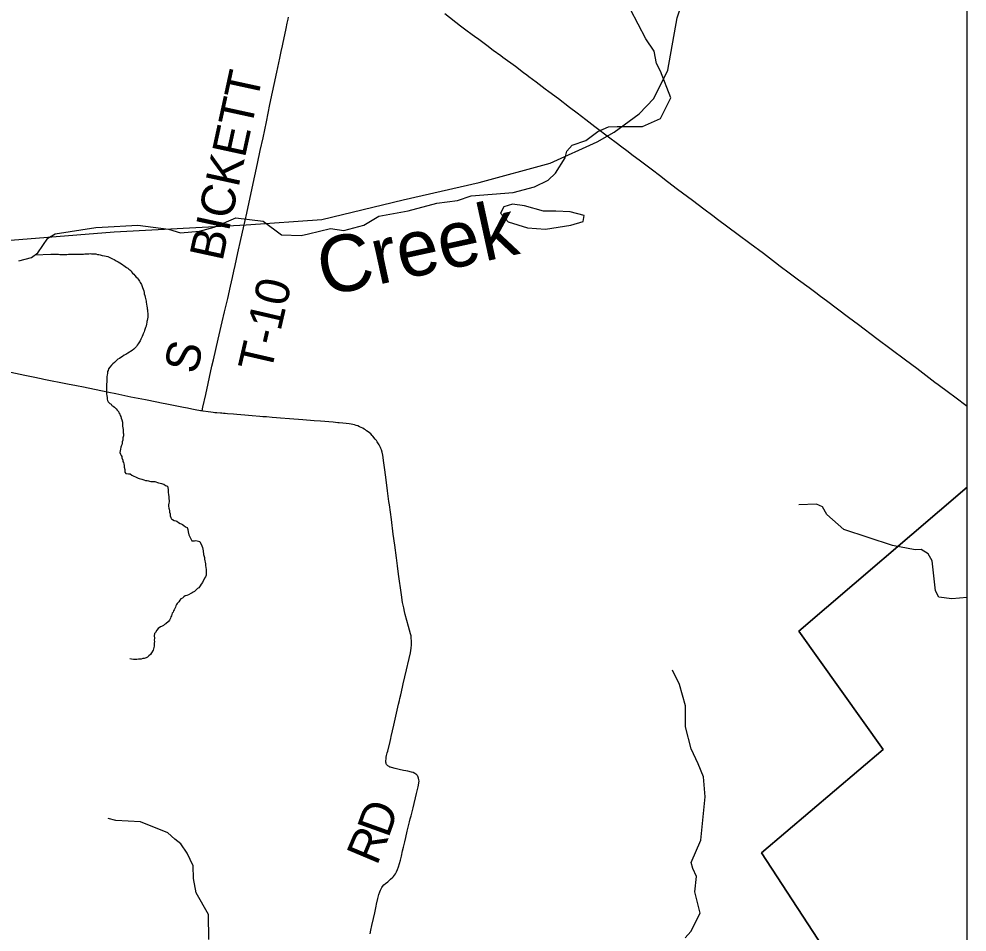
# Model space of a CAD drawing. Extents: x -1.4 to 35.4, y 0 to 22.
# Drawn here: x 14.841 to 16.43, y 16.794 to 18.324 of the extents above; entities that cross this region are included whole.
import ezdxf

# ---------------------------------------------------------------- set-up
doc = ezdxf.new("R2010")
doc.units = 0
for name, color, linetype in [('GM_X_County_Road', 7, 'Continuous'), ('GM_X_Minor_Lake', 7, 'Continuous'), ('GM_X_Minor_River', 7, 'Continuous'), ('GM_X_Minor_River_Text', 7, 'Continuous'), ('GM_X_Rail_Line', 7, 'Continuous'), ('GM_X_Township_Road', 7, 'Continuous'), ('GM_X_Township_Road_Text', 7, 'Continuous'), ('SC_Scratch1', 7, 'Continuous'), ('SH_Border', 7, 'Continuous')]:
    doc.layers.add(name, color=color, linetype=linetype)

msp = doc.modelspace()

# ---------------------------------------------------------------- linework, layer by layer
at = {"layer": 'GM_X_County_Road'}
msp.add_lwpolyline([(16.4299, 17.6747), (16.4096, 17.6899), (16.3991, 17.6977), (16.3817, 17.7106), (16.3762, 17.7147), (16.3455, 17.7379), (16.3266, 17.7521), (16.2789, 17.7879), (16.2483, 17.8113), (16.2314, 17.8239), (16.1945, 17.8514), (16.1845, 17.8588), (16.1766, 17.8648), (16.1652, 17.8734), (16.1476, 17.8862), (16.1317, 17.898), (16.1168, 17.9093), (16.1089, 17.9153), (16.0886, 17.9308), (16.0657, 17.9478), (16.0463, 17.9623), (16.012, 17.988), (16.004, 17.9939), (15.9891, 18.0052), (15.9698, 18.0197), (15.945, 18.0384), (15.9282, 18.0513), (15.9144, 18.0619), (15.9028, 18.0707), (15.8807, 18.0874), (15.8706, 18.0947), (15.8598, 18.1028), (15.8513, 18.1091), (15.8419, 18.1163), (15.8315, 18.1242), (15.8064, 18.1435), (15.7911, 18.1551), (15.7768, 18.1661), (15.7639, 18.1758), (15.7451, 18.19), (15.7291, 18.2018), (15.7232, 18.2063), (15.7078, 18.2179), (15.6959, 18.2269), (15.692, 18.23), (15.6865, 18.234), (15.6731, 18.2442), (15.6522, 18.2597), (15.6487, 18.2623), (15.6361, 18.2714), (15.625, 18.2795), (15.6117, 18.2894), (15.6047, 18.2946), (15.6007, 18.2976), (15.5903, 18.3054), (15.5814, 18.3122), (15.5547, 18.3324)], dxfattribs=at)
at = {"layer": 'GM_X_Minor_Lake'}
for points in [[(15.6885, 18.011), (15.6684, 18.0136), (15.6535, 18.0089), (15.648, 17.9988), (15.661, 17.9838), (15.6935, 17.9741), (15.7235, 17.972), (15.7661, 17.9782), (15.7867, 17.9843), (15.7884, 17.9949), (15.765, 18.001), (15.7411, 18.0017), (15.7202, 18.0021)], [(15.7202, 18.0021), (15.6885, 18.011)]]:
    msp.add_lwpolyline(points, dxfattribs=at)
at = {"layer": 'GM_X_Minor_River'}
for points in [[(14.9805, 17.9749), (15.0405, 17.9785), (15.0917, 17.9715), (15.1117, 17.9658), (15.1436, 17.9683), (15.1681, 17.9751), (15.2044, 17.9905), (15.2506, 17.9851), (15.281, 17.9625), (15.314, 17.9612), (15.3266, 17.964), (15.3632, 17.9729), (15.3859, 17.9695), (15.4191, 17.9784), (15.4444, 17.9935), (15.4932, 18.0026), (15.5412, 18.0151), (15.5759, 18.0198), (15.5988, 18.0277), (15.6691, 18.033), (15.705, 18.0426), (15.7283, 18.054), (15.7403, 18.0656), (15.7567, 18.0915), (15.7595, 18.1025), (15.768, 18.1126), (15.791, 18.1205), (15.811, 18.1354), (15.8293, 18.1434), (15.8438, 18.1436), (15.8859, 18.144), (15.9161, 18.1575), (15.9334, 18.1918), (15.916, 18.2365), (15.9097, 18.2495), (15.9055, 18.2701), (15.8918, 18.2909), (15.8532, 18.3648)], [(14.8409, 17.9188), (14.8623, 17.9245), (14.8727, 17.9323), (14.8898, 17.9567), (14.9021, 17.9641), (14.9702, 17.9743), (14.9805, 17.9749)], [(14.8683, 17.9285), (14.8945, 17.9296), (14.8987, 17.9299), (14.9021, 17.9299), (14.9055, 17.9299), (14.9074, 17.9299), (14.91, 17.9294), (14.9131, 17.929), (14.9157, 17.929), (14.9184, 17.929), (14.9214, 17.9294), (14.9241, 17.9297), (14.9271, 17.9297), (14.929, 17.93), (14.9313, 17.93), (14.9339, 17.93), (14.9358, 17.93), (14.9377, 17.93), (14.94, 17.9299), (14.943, 17.9299), (14.9453, 17.9299), (14.9472, 17.9299), (14.9495, 17.9299), (14.9514, 17.9302), (14.9544, 17.9306), (14.9563, 17.9302), (14.9586, 17.9305), (14.9605, 17.9309), (14.9631, 17.9305), (14.9673, 17.9301), (14.9703, 17.9301), (14.973, 17.9293), (14.9752, 17.9293), (14.9771, 17.9289), (14.979, 17.9281), (14.9809, 17.9277), (14.9847, 17.9273), (14.99, 17.9257), (14.9926, 17.9246), (14.996, 17.923), (14.9979, 17.9222), (15.0006, 17.9207), (15.0024, 17.9195), (15.0043, 17.9188), (15.0073, 17.9168), (15.0104, 17.9153), (15.013, 17.9138), (15.0153, 17.9118), (15.0172, 17.9107), (15.019, 17.9091), (15.0217, 17.9072), (15.0236, 17.9061), (15.0254, 17.9049), (15.0285, 17.9022), (15.03, 17.9003), (15.0318, 17.898), (15.0337, 17.8961), (15.0356, 17.8938), (15.0375, 17.8915), (15.0393, 17.89), (15.0408, 17.8877), (15.0435, 17.8843), (15.0446, 17.8824), (15.0465, 17.8789), (15.048, 17.8759), (15.0483, 17.874), (15.0494, 17.8709), (15.0505, 17.8683), (15.0509, 17.8656), (15.0513, 17.8633), (15.052, 17.8607), (15.0527, 17.858), (15.0535, 17.8557), (15.0542, 17.8511), (15.0546, 17.8492), (15.0549, 17.8458), (15.0556, 17.8428), (15.056, 17.8401), (15.056, 17.8382), (15.0564, 17.8363), (15.0567, 17.8329), (15.0571, 17.831), (15.057, 17.8276), (15.057, 17.8242), (15.0566, 17.8215), (15.0562, 17.8189), (15.0558, 17.817), (15.0558, 17.8151), (15.055, 17.8128), (15.0542, 17.809), (15.0535, 17.8071), (15.0523, 17.8037), (15.0519, 17.8018), (15.0508, 17.7999), (15.0496, 17.7965), (15.0488, 17.7946), (15.0477, 17.792), (15.0465, 17.7897), (15.0453, 17.7871), (15.0442, 17.7848), (15.0423, 17.7814)], [(15.0423, 17.7814), (15.0411, 17.7795), (15.0396, 17.7773), (15.038, 17.775), (15.0357, 17.7724), (15.0335, 17.7705), (15.0312, 17.7682), (15.0239, 17.7637), (15.022, 17.763), (15.0201, 17.7615), (15.0178, 17.7604), (15.0148, 17.7585), (15.0117, 17.7566), (15.0095, 17.7551), (15.0072, 17.7536), (15.0049, 17.7518), (15.003, 17.7499), (15.0011, 17.748), (14.9988, 17.7461), (14.9961, 17.7439), (14.9934, 17.7405), (14.9915, 17.7375), (14.9907, 17.7348), (14.9899, 17.7329), (14.9895, 17.7303), (14.9891, 17.7268), (14.9887, 17.7246), (14.9887, 17.7219), (14.9887, 17.7196), (14.9887, 17.7177), (14.9883, 17.7151), (14.9879, 17.7124), (14.9879, 17.7102), (14.9882, 17.7075), (14.9878, 17.7056), (14.9882, 17.6995), (14.9881, 17.6976), (14.9881, 17.6957), (14.9885, 17.6923), (14.9888, 17.6897), (14.9892, 17.687), (14.9899, 17.6847), (14.9907, 17.6824), (14.9933, 17.6797), (14.9956, 17.6782), (14.9971, 17.6763), (14.9993, 17.6748), (15.0016, 17.6732), (15.0042, 17.6705), (15.0057, 17.6686), (15.008, 17.666), (15.0087, 17.6637), (15.0102, 17.6618), (15.011, 17.6595), (15.0121, 17.6576), (15.0128, 17.6549), (15.0136, 17.6522), (15.0147, 17.6484), (15.015, 17.6446), (15.015, 17.6416), (15.0153, 17.6386), (15.0157, 17.6359), (15.0157, 17.634), (15.016, 17.6306), (15.0164, 17.6287), (15.0164, 17.6253), (15.0156, 17.6222), (15.0156, 17.6203), (15.0155, 17.6181), (15.0144, 17.6154), (15.014, 17.6131), (15.0136, 17.6101), (15.0128, 17.6082), (15.012, 17.6063), (15.0116, 17.6029), (15.0109, 17.5999), (15.0105, 17.5976), (15.0116, 17.5946), (15.0123, 17.5923), (15.0134, 17.5904), (15.0138, 17.5885), (15.0153, 17.5847), (15.0156, 17.5824), (15.0164, 17.5805), (15.0171, 17.5782), (15.0175, 17.5755), (15.0178, 17.5729), (15.0186, 17.5691), (15.0185, 17.5664), (15.0185, 17.5645), (15.0204, 17.5622), (15.0246, 17.5618), (15.0276, 17.5614), (15.0302, 17.5595), (15.034, 17.5579), (15.0367, 17.5564), (15.0389, 17.5556), (15.0408, 17.5545), (15.0427, 17.5537), (15.0469, 17.5525), (15.0503, 17.5514)], [(15.0503, 17.5514), (15.0533, 17.5506), (15.0559, 17.5505), (15.0582, 17.5498), (15.0601, 17.5494), (15.062, 17.549), (15.0639, 17.549), (15.0662, 17.5486), (15.0688, 17.5485), (15.0707, 17.5481), (15.0733, 17.547), (15.0752, 17.5466), (15.0779, 17.5458), (15.0802, 17.5454), (15.082, 17.5446), (15.0843, 17.5442), (15.087, 17.5423), (15.09, 17.5411), (15.0911, 17.5354), (15.0914, 17.5305), (15.0921, 17.5267), (15.0925, 17.5233), (15.0925, 17.5199), (15.0928, 17.5172), (15.0928, 17.5149), (15.0924, 17.5123), (15.092, 17.5096), (15.092, 17.5077), (15.0923, 17.5043), (15.0927, 17.5024), (15.0934, 17.4997), (15.0934, 17.4975), (15.0945, 17.4948), (15.0949, 17.4914), (15.0956, 17.4887), (15.0964, 17.4864), (15.0986, 17.4849), (15.1016, 17.4834), (15.1039, 17.4826), (15.1058, 17.4822), (15.1084, 17.4803), (15.1115, 17.4783), (15.1133, 17.4776), (15.1152, 17.4768), (15.1175, 17.4752), (15.1205, 17.4726), (15.1231, 17.4714), (15.1243, 17.4684), (15.125, 17.4645), (15.1261, 17.4596), (15.1268, 17.4569), (15.1309, 17.4493), (15.1355, 17.4493), (15.1378, 17.45), (15.1419, 17.4488), (15.1446, 17.4484), (15.1479, 17.4408), (15.149, 17.4382), (15.1497, 17.4325), (15.1505, 17.4264), (15.1519, 17.4214), (15.1523, 17.4184), (15.1526, 17.4157), (15.1534, 17.4134), (15.1537, 17.4108), (15.1541, 17.4077), (15.1544, 17.4047), (15.1548, 17.4013), (15.1548, 17.3986), (15.1551, 17.3956), (15.1547, 17.3918), (15.1536, 17.3888), (15.1524, 17.3865), (15.1486, 17.3793), (15.1466, 17.3767), (15.1451, 17.3741), (15.1428, 17.3707), (15.1405, 17.3692), (15.1371, 17.3658), (15.1352, 17.3643), (15.1333, 17.3631), (15.1314, 17.362), (15.1295, 17.3613), (15.1253, 17.3587), (15.1226, 17.3579), (15.1199, 17.3572), (15.1177, 17.3553), (15.1154, 17.3534), (15.1127, 17.3519), (15.1108, 17.3497), (15.1089, 17.347), (15.1066, 17.3444), (15.105, 17.3425), (15.1043, 17.3403), (15.1035, 17.3384), (15.1023, 17.3361), (15.1012, 17.3338), (15.1004, 17.3319), (15.0996, 17.33), (15.0981, 17.3278), (15.0977, 17.3259)], [(16.4299, 17.3545), (16.4044, 17.3519), (16.3828, 17.3548), (16.3769, 17.3656), (16.3716, 17.4157), (16.3646, 17.4276), (16.3533, 17.435), (16.3431, 17.4344), (16.3049, 17.4414), (16.2237, 17.4681), (16.1949, 17.4936), (16.1879, 17.5062), (16.1774, 17.5105), (16.1482, 17.5098)], [(15.0977, 17.3259), (15.0969, 17.3236), (15.0958, 17.3217), (15.0954, 17.3195), (15.0935, 17.3161), (15.0916, 17.3142), (15.0873, 17.31), (15.0851, 17.3089), (15.0832, 17.3074), (15.0801, 17.3059), (15.0782, 17.3052), (15.0748, 17.3022), (15.0725, 17.2995), (15.0702, 17.2958), (15.0686, 17.2939), (15.0679, 17.2901), (15.0682, 17.2859), (15.0678, 17.2829), (15.0682, 17.2806), (15.0678, 17.2776), (15.0681, 17.2757), (15.0681, 17.273), (15.0673, 17.2707), (15.0669, 17.2685), (15.0662, 17.2662), (15.0635, 17.2617), (15.0615, 17.259), (15.0589, 17.2568), (15.0566, 17.2545), (15.0543, 17.253), (15.0513, 17.2519), (15.0486, 17.2519), (15.0459, 17.2512), (15.0414, 17.2509), (15.0387, 17.2505), (15.0368, 17.2505), (15.033, 17.2502), (15.0296, 17.251), (15.027, 17.2514)], [(15.9576, 16.784), (15.9673, 16.7944), (15.9826, 16.8253), (15.9737, 16.8608), (15.9768, 16.8869), (15.9706, 16.8999), (15.9677, 16.9102), (15.9839, 16.9476), (15.9912, 17.0203), (15.9884, 17.0538), (15.9793, 17.0756), (15.9679, 17.1009), (15.9579, 17.1375), (15.9581, 17.1728), (15.9481, 17.2083), (15.9364, 17.2324)], [(15.1594, 16.7809), (15.159, 16.8231), (15.138, 16.8591), (15.1335, 16.8835), (15.1334, 16.9044), (15.1232, 16.9259), (15.1124, 16.9412), (15.1027, 16.9494), (15.0907, 16.9598), (15.0447, 16.9781), (15.0034, 16.9803), (14.9909, 16.9839)]]:
    msp.add_lwpolyline(points, dxfattribs=at)
at = {"layer": 'GM_X_Rail_Line'}
msp.add_lwpolyline([(14.8273, 17.9533), (15.001, 17.9673), (15.2222, 17.9788), (15.3486, 17.988), (15.4848, 18.0208), (15.6125, 18.0501), (15.7313, 18.0824), (15.8102, 18.1181), (15.8388, 18.1341), (15.8805, 18.1649), (15.9051, 18.191), (15.9285, 18.238), (15.944, 18.3262), (15.9577, 18.3667), (15.9803, 18.4028), (16.0139, 18.4405), (16.164, 18.5813), (16.2878, 18.6917), (16.3423, 18.7301), (16.4022, 18.7499), (16.4299, 18.7533)], dxfattribs=at)
at = {"layer": 'GM_X_Township_Road'}
for points in [[(15.1481, 17.667), (15.1495, 17.6733), (15.1542, 17.6945), (15.1646, 17.7419), (15.1671, 17.7528), (15.1751, 17.7873), (15.182, 17.8163), (15.1858, 17.8333), (15.1912, 17.8556), (15.1958, 17.8762), (15.199, 17.8908), (15.2012, 17.9011), (15.2033, 17.9108), (15.2081, 17.932), (15.213, 17.9543), (15.2175, 17.9738), (15.2232, 17.9987), (15.2323, 18.0404), (15.241, 18.0817), (15.2457, 18.1036), (15.2502, 18.1249), (15.2558, 18.1517), (15.2618, 18.1809), (15.2734, 18.2349), (15.2786, 18.2586), (15.2809, 18.2695), (15.2828, 18.2793), (15.2833, 18.2817), (15.2888, 18.3078), (15.2907, 18.3169), (15.2921, 18.3236), (15.2928, 18.3273)], [(15.1481, 17.667), (15.1454, 17.6674), (15.1363, 17.6691), (15.131, 17.6702), (15.1236, 17.6716), (15.1168, 17.6729), (15.0891, 17.6785), (15.0802, 17.6802), (15.0722, 17.6818), (15.0531, 17.6856), (15.0289, 17.6903), (15.0035, 17.6955), (14.9916, 17.6981), (14.9811, 17.7002), (14.968, 17.7029), (14.9493, 17.7067), (14.9375, 17.709), (14.9225, 17.7119), (14.8831, 17.72), (14.8786, 17.7209), (14.8653, 17.7237), (14.8513, 17.7266), (14.8274, 17.7313)], [(15.4329, 17.6261), (15.4306, 17.6285), (15.4262, 17.6322), (15.4238, 17.6339), (15.4219, 17.6352), (15.4195, 17.6367), (15.4172, 17.638), (15.4148, 17.6392), (15.412, 17.6405), (15.4091, 17.6418), (15.4064, 17.6427), (15.4035, 17.6436), (15.4008, 17.6443), (15.3977, 17.645), (15.3946, 17.6455), (15.3897, 17.646), (15.3841, 17.6466), (15.378, 17.6472), (15.3755, 17.6473), (15.3675, 17.6481), (15.3465, 17.6498), (15.3359, 17.6506), (15.3167, 17.652), (15.2944, 17.6539), (15.2796, 17.6551), (15.2728, 17.6556), (15.2653, 17.6562), (15.2561, 17.6569), (15.2499, 17.6574), (15.2449, 17.6579), (15.2319, 17.659), (15.2257, 17.6594), (15.2196, 17.6601), (15.2066, 17.6612), (15.201, 17.6615), (15.1906, 17.6624), (15.1869, 17.6628), (15.1838, 17.663), (15.1814, 17.6632), (15.179, 17.6634), (15.173, 17.6638), (15.1696, 17.6641), (15.1665, 17.6644), (15.1626, 17.6648), (15.1583, 17.6654), (15.1497, 17.6668), (15.1481, 17.667)], [(15.4296, 16.7903), (15.4311, 16.797), (15.4327, 16.8043), (15.4354, 16.8164), (15.4374, 16.8255), (15.4399, 16.837), (15.4405, 16.8401), (15.4427, 16.8498), (15.4445, 16.8564), (15.446, 16.8612), (15.447, 16.8636), (15.4482, 16.8662), (15.4494, 16.8685), (15.4505, 16.8701), (15.4528, 16.8727), (15.4553, 16.875), (15.4591, 16.878), (15.464, 16.8821), (15.4679, 16.8856), (15.4691, 16.8869), (15.4705, 16.8887), (15.4723, 16.8914), (15.474, 16.8947), (15.4756, 16.8984), (15.4773, 16.9029), (15.479, 16.9086), (15.4805, 16.9143), (15.4821, 16.9206), (15.4841, 16.9297), (15.4856, 16.9356), (15.4877, 16.9448), (15.4895, 16.9521), (15.492, 16.9626), (15.4941, 16.9717), (15.4958, 16.9783), (15.497, 16.9831), (15.4983, 16.9886), (15.5016, 17.0018), (15.5075, 17.026), (15.5102, 17.0368), (15.5109, 17.0398), (15.5114, 17.0435), (15.5116, 17.0465), (15.5114, 17.0488), (15.5108, 17.0517), (15.5102, 17.0532), (15.5094, 17.0549), (15.5087, 17.0559), (15.5077, 17.0571), (15.5064, 17.0582), (15.5046, 17.0594), (15.5018, 17.0608), (15.4992, 17.0615), (15.4926, 17.063), (15.4895, 17.0637), (15.4855, 17.0646), (15.4782, 17.0663), (15.4716, 17.0677), (15.4656, 17.0692), (15.4641, 17.0698), (15.4629, 17.0702), (15.4615, 17.0709), (15.4604, 17.0716), (15.4591, 17.0724), (15.458, 17.0734), (15.4572, 17.0744), (15.4566, 17.0755), (15.4563, 17.0769), (15.4561, 17.0784), (15.4561, 17.0807), (15.4563, 17.0837), (15.4566, 17.0865), (15.4573, 17.0896), (15.4583, 17.0939), (15.4591, 17.0969), (15.4632, 17.1131), (15.4643, 17.118), (15.4651, 17.1216), (15.4694, 17.1403), (15.4739, 17.1603), (15.4774, 17.1755), (15.4787, 17.1815), (15.4796, 17.1851), (15.481, 17.1912), (15.4839, 17.2039), (15.4851, 17.2094), (15.4906, 17.233), (15.4923, 17.2402), (15.4929, 17.2427), (15.4971, 17.2614), (15.4979, 17.2654), (15.4985, 17.2693), (15.499, 17.2748), (15.4991, 17.2809), (15.4986, 17.287), (15.4982, 17.2901), (15.4974, 17.2936), (15.4942, 17.3058), (15.4886, 17.326), (15.4873, 17.3308), (15.4859, 17.3369), (15.484, 17.346), (15.482, 17.359), (15.4773, 17.3934), (15.4755, 17.4076), (15.4738, 17.4206), (15.4709, 17.4421), (15.4685, 17.4606), (15.4653, 17.4852), (15.4637, 17.4975), (15.462, 17.5099), (15.4613, 17.5154), (15.4589, 17.5333), (15.4563, 17.5517), (15.4542, 17.5684), (15.4526, 17.5801), (15.4509, 17.593), (15.4499, 17.5978), (15.4487, 17.6018), (15.4478, 17.6042), (15.4471, 17.6058), (15.4449, 17.6102), (15.4417, 17.6154), (15.4401, 17.6176), (15.4384, 17.6198), (15.4345, 17.6245), (15.4329, 17.6261)]]:
    msp.add_lwpolyline(points, dxfattribs=at)
at = {"layer": 'SC_Scratch1'}
for points in [[(16.3183, 16.5692), (16.0855, 16.9264), (16.2895, 17.0993), (16.1482, 17.2981), (16.4299, 17.5391), (16.4299, 19.8546), (10.6405, 19.8546)], [(16.4299, 15.2626), (16.4299, 17.5391), (16.1482, 17.2981), (16.2895, 17.0993), (16.0855, 16.9264), (16.3183, 16.5692)]]:
    msp.add_lwpolyline(points, dxfattribs=at)
at = {"layer": 'SH_Border'}
msp.add_lwpolyline([(9.6299, 19.8546), (9.6299, 13.0546), (16.4299, 13.0546), (16.4299, 19.8546)], close=True, dxfattribs=at)

# ---------------------------------------------------------------- texts
at = {"layer": 'GM_X_Minor_River_Text'}
msp.add_text('Creek', height=0.09469, rotation=12.3144, dxfattribs=at).set_placement((15.3527, 17.8588))
at = {"layer": 'GM_X_Township_Road_Text'}
for s, height, rotation, p in [('BICKETT', 0.05682, 77.7422, (15.1821, 17.9165)), ('T-10', 0.05682, 76.9793, (15.2633, 17.7294)), ('S', 0.0568, 76.51, (15.1387, 17.7271)), ('D', 0.0568, 70.2469, (15.4602, 16.9498)), ('R', 0.0568, 67.1396, (15.4409, 16.9037))]:
    msp.add_text(s, height=height, rotation=rotation, dxfattribs=at).set_placement(p)

doc.saveas('drawing.dxf')
